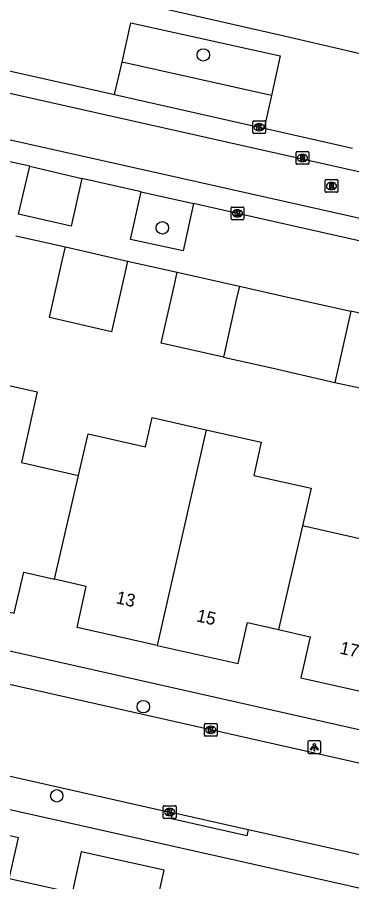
# Model space of a CAD drawing. Extents: x 161771 to 163125, y 382479 to 383177.
# Drawn here: x 162664.1 to 162690.4, y 382742 to 382809.9 of the extents above; entities that cross this region are included whole.
import ezdxf

# ---------------------------------------------------------------- set-up
doc = ezdxf.new("R2010")
doc.units = 0
for name, color, linetype in [('IMGEO_Boom', 7, 'Continuous'), ('IMGEO_Kolk', 7, 'Continuous'), ('IMGEO_Lichtpunt', 7, 'Continuous'), ('IMGEO_Pand', 7, 'Continuous'), ('IMGEO_Pand_nummerreeks', 7, 'Continuous'), ('IMGEO_Parkeervlak_open', 7, 'Continuous'), ('IMGEO_Rijbaan_lokaal_gesloten', 7, 'Continuous'), ('IMGEO_Rijbaan_lokaal_open', 7, 'Continuous'), ('IMGEO_Rioolput', 7, 'Continuous'), ('IMGEO_Voetpad_open', 7, 'Continuous')]:
    doc.layers.add(name, color=color, linetype=linetype)

msp = doc.modelspace()

# ---------------------------------------------------------------- linework, layer by layer
at = {"layer": 'IMGEO_Boom'}
for centre in [(162678.704, 382806.959), (162675.491, 382793.374), (162673.998, 382755.754), (162667.2, 382748.751)]:
    msp.add_circle(centre, 0.489, dxfattribs=at)
at = {"layer": 'IMGEO_Kolk'}
for p, q in [((162682.586, 382800.854), (162682.586, 382801.706)), ((162682.661, 382801.78), (162683.513, 382801.78)), ((162683.074, 382801.56), (162683.099, 382801.56)), ((162683.587, 382801.706), (162683.587, 382800.854)), ((162683.513, 382800.78), (162682.661, 382800.78)), ((162683.097, 382801), (162683.072, 382801)), ((162680.892, 382794.082), (162680.892, 382794.934)), ((162680.967, 382795.008), (162681.819, 382795.008)), ((162681.38, 382794.788), (162681.405, 382794.788)), ((162681.893, 382794.934), (162681.893, 382794.082)), ((162681.819, 382794.008), (162680.967, 382794.008)), ((162681.403, 382794.228), (162681.378, 382794.228)), ((162678.786, 382753.508), (162678.786, 382754.36)), ((162678.861, 382754.434), (162679.713, 382754.434)), ((162679.274, 382754.214), (162679.299, 382754.214)), ((162679.787, 382754.36), (162679.787, 382753.508)), ((162679.713, 382753.434), (162678.861, 382753.434)), ((162679.297, 382753.654), (162679.272, 382753.654)), ((162675.562, 382747.051), (162675.562, 382747.903)), ((162675.637, 382747.977), (162676.489, 382747.977)), ((162676.05, 382747.757), (162676.075, 382747.757)), ((162676.563, 382747.903), (162676.563, 382747.051)), ((162676.073, 382747.197), (162676.048, 382747.197)), ((162676.489, 382746.977), (162675.637, 382746.977))]:
    msp.add_line(p, q, dxfattribs=at)
for points in [[(162682.586, 382800.854), (162682.586, 382801.706)], [(162682.661, 382801.78), (162683.513, 382801.78)], [(162682.907, 382801.48), (162683.03, 382801.48), (162683.03, 382801.329), (162683.16, 382801.48), (162683.324, 382801.48), (162683.178, 382801.329), (162683.331, 382801.08), (162683.179, 382801.08), (162683.094, 382801.244), (162683.03, 382801.177), (162683.03, 382801.08), (162682.907, 382801.08), (162682.907, 382801.48)], [(162683.587, 382801.706), (162683.587, 382800.854)], [(162683.513, 382800.78), (162682.661, 382800.78)], [(162680.892, 382794.082), (162680.892, 382794.934)], [(162680.967, 382795.008), (162681.819, 382795.008)], [(162681.213, 382794.708), (162681.336, 382794.708), (162681.336, 382794.557), (162681.466, 382794.708), (162681.63, 382794.708), (162681.484, 382794.557), (162681.637, 382794.308), (162681.485, 382794.308), (162681.4, 382794.472), (162681.336, 382794.405), (162681.336, 382794.308), (162681.213, 382794.308), (162681.213, 382794.708)], [(162681.893, 382794.934), (162681.893, 382794.082)], [(162681.819, 382794.008), (162680.967, 382794.008)], [(162678.786, 382753.508), (162678.786, 382754.36)], [(162678.861, 382754.434), (162679.713, 382754.434)], [(162679.107, 382754.134), (162679.23, 382754.134), (162679.23, 382753.983), (162679.36, 382754.134), (162679.524, 382754.134), (162679.378, 382753.983), (162679.531, 382753.734), (162679.379, 382753.734), (162679.294, 382753.898), (162679.23, 382753.831), (162679.23, 382753.734), (162679.107, 382753.734), (162679.107, 382754.134)], [(162679.787, 382754.36), (162679.787, 382753.508)], [(162679.713, 382753.434), (162678.861, 382753.434)], [(162675.562, 382747.051), (162675.562, 382747.903)], [(162675.637, 382747.977), (162676.489, 382747.977)], [(162676.563, 382747.903), (162676.563, 382747.051)], [(162675.883, 382747.677), (162676.006, 382747.677), (162676.006, 382747.526), (162676.136, 382747.677), (162676.3, 382747.677), (162676.154, 382747.526), (162676.307, 382747.277), (162676.155, 382747.277), (162676.07, 382747.441), (162676.006, 382747.374), (162676.006, 382747.277), (162675.883, 382747.277), (162675.883, 382747.677)], [(162676.489, 382746.977), (162675.637, 382746.977)]]:
    msp.add_lwpolyline(points, dxfattribs=at)
for centre, start, end in [((162682.663, 382801.704), 91.55205, 178.44795), ((162682.663, 382801.704), 91.55205, 178.44795), ((162683.511, 382801.704), 1.55205, 88.44795), ((162683.511, 382801.704), 1.55205, 88.44795), ((162682.663, 382800.856), 181.55205, 268.44795), ((162682.663, 382800.856), 181.55205, 268.44795), ((162683.511, 382800.856), 271.55205, 358.44795), ((162683.511, 382800.856), 271.55205, 358.44795), ((162680.969, 382794.932), 91.55205, 178.44795), ((162680.969, 382794.932), 91.55205, 178.44795), ((162681.817, 382794.932), 1.55205, 88.44795), ((162681.817, 382794.932), 1.55205, 88.44795), ((162680.969, 382794.084), 181.55205, 268.44795), ((162680.969, 382794.084), 181.55205, 268.44795), ((162681.817, 382794.084), 271.55205, 358.44795), ((162681.817, 382794.084), 271.55205, 358.44795), ((162678.863, 382754.358), 91.55205, 178.44795), ((162678.863, 382754.358), 91.55205, 178.44795), ((162679.711, 382754.358), 1.55205, 88.44795), ((162679.711, 382754.358), 1.55205, 88.44795), ((162678.863, 382753.51), 181.55205, 268.44795), ((162678.863, 382753.51), 181.55205, 268.44795), ((162679.711, 382753.51), 271.55205, 358.44795), ((162679.711, 382753.51), 271.55205, 358.44795), ((162675.639, 382747.901), 91.55205, 178.44795), ((162675.639, 382747.901), 91.55205, 178.44795), ((162676.487, 382747.901), 1.55205, 88.44795), ((162676.487, 382747.901), 1.55205, 88.44795), ((162675.639, 382747.053), 181.55205, 268.44795), ((162675.639, 382747.053), 181.55205, 268.44795), ((162676.487, 382747.053), 271.55205, 358.44795), ((162676.487, 382747.053), 271.55205, 358.44795)]:
    msp.add_arc(centre, 0.0765, start, end, dxfattribs=at)
for centre, major_axis, ratio, start_param, end_param in [((162683.073, 382801.28), (-0.387, 0.002), 0.722429, 4.712389, 7.853982), ((162683.098, 382801.28), (-0.39, 0.002), 0.717154, 1.570796, 4.712389), ((162681.379, 382794.508), (-0.387, 0.002), 0.722429, 4.712389, 7.853982), ((162681.404, 382794.508), (-0.39, 0.002), 0.717154, 1.570796, 4.712389), ((162679.273, 382753.934), (-0.387, 0.002), 0.722429, 4.712389, 7.853982), ((162679.298, 382753.934), (-0.39, 0.002), 0.717154, 1.570796, 4.712389), ((162676.049, 382747.477), (-0.387, 0.002), 0.722429, 4.712389, 7.853982), ((162676.074, 382747.477), (-0.39, 0.002), 0.717154, 1.570796, 4.712389)]:
    msp.add_ellipse(centre, major_axis=major_axis, ratio=ratio, start_param=start_param, end_param=end_param, dxfattribs=at)
at = {"layer": 'IMGEO_Lichtpunt'}
for p, q in [((162686.923, 382752.978), (162686.923, 382752.171)), ((162686.923, 382752.978), (162686.923, 382752.171)), ((162687.825, 382753.073), (162687.017, 382753.073)), ((162687.825, 382753.073), (162687.017, 382753.073)), ((162687.919, 382752.171), (162687.919, 382752.978)), ((162687.919, 382752.171), (162687.919, 382752.978)), ((162687.017, 382752.077), (162687.825, 382752.077)), ((162687.017, 382752.077), (162687.825, 382752.077))]:
    msp.add_line(p, q, dxfattribs=at)
for points in [[(162687.297, 382752.642), (162687.336, 382752.614), (162687.148, 382752.352), (162687.11, 382752.379), (162687.297, 382752.642)], [(162687.399, 382752.594), (162687.446, 382752.594), (162687.446, 382752.272), (162687.399, 382752.272), (162687.399, 382752.594)], [(162687.509, 382752.614), (162687.547, 382752.641), (162687.734, 382752.379), (162687.695, 382752.351), (162687.509, 382752.614)]]:
    msp.add_lwpolyline(points, dxfattribs=at)
msp.add_circle((162687.422, 382752.776), 0.0994, dxfattribs=at)
for centre, start, end in [((162687.017, 382752.978), 90, 180), ((162687.017, 382752.978), 90, 180), ((162687.825, 382752.978), 0, 90), ((162687.825, 382752.978), 0, 90), ((162687.017, 382752.171), 180, 270), ((162687.017, 382752.171), 180, 270), ((162687.825, 382752.171), 270, 0), ((162687.825, 382752.171), 270, 360)]:
    msp.add_arc(centre, 0.0946, start, end, dxfattribs=at)
at = {"layer": 'IMGEO_Pand'}
for points in [[(162672.76, 382790.762), (162672.514, 382789.669), (162671.509, 382785.202), (162666.628, 382786.325), (162667.633, 382790.793), (162667.879, 382791.885)], [(162667.879, 382791.885), (162672.76, 382790.762)], [(162680.282, 382783.204), (162675.406, 382784.326), (162676.411, 382788.793), (162676.657, 382789.886)], [(162676.657, 382789.886), (162681.541, 382788.799)], [(162681.541, 382788.799), (162681.295, 382787.707), (162680.282, 382783.204)], [(162681.541, 382788.799), (162685.433, 382787.914), (162690.298, 382786.827)], [(162690.298, 382786.827), (162689.039, 382781.236)], [(162699.098, 382784.822), (162694.217, 382785.945), (162690.298, 382786.827)], [(162680.282, 382783.204), (162684.182, 382782.354), (162689.039, 382781.236)], [(162661.453, 382781.444), (162665.669, 382780.495), (162664.419, 382774.934), (162668.911, 382773.924)], [(162689.039, 382781.236), (162692.966, 382780.385), (162693.545, 382780.252), (162692.254, 382774.515), (162691.004, 382768.954), (162686.501, 382769.967)], [(162668.911, 382773.924), (162669.659, 382777.18), (162674.166, 382776.167), (162674.683, 382778.468), (162678.94, 382777.51)], [(162678.94, 382777.51), (162675.082, 382760.567)], [(162678.94, 382777.51), (162683.249, 382776.541), (162682.662, 382773.928), (162687.165, 382772.915), (162686.501, 382769.967)], [(162667.031, 382765.765), (162668.911, 382773.924)], [(162686.501, 382769.967), (162684.61, 382761.808)], [(162657.549, 382764.513), (162663.861, 382763.093), (162664.603, 382766.312), (162667.031, 382765.765)], [(162675.082, 382760.567), (162668.794, 382761.982), (162669.52, 382765.205), (162667.031, 382765.765)], [(162675.082, 382760.567), (162681.44, 382759.137), (162682.173, 382762.357), (162684.61, 382761.808)], [(162684.61, 382761.808), (162687.1, 382761.248), (162686.374, 382758.026), (162692.669, 382756.609)], [(162665.955, 382741.686), (162663.475, 382742.24), (162664.194, 382745.46), (162657.734, 382746.937), (162656.532, 382741.659), (162653.794, 382742.271)], [(162677.22, 382737.05), (162674.452, 382737.668), (162675.622, 382742.908), (162669.123, 382744.359), (162668.404, 382741.139), (162665.955, 382741.686)]]:
    msp.add_lwpolyline(points, dxfattribs=at)
at = {"layer": 'IMGEO_Parkeervlak_open'}
msp.add_lwpolyline([(162684.05, 382803.775), (162672.334, 382806.402)], dxfattribs=at)
at = {"layer": 'IMGEO_Rijbaan_lokaal_gesloten'}
for points in [[(163032.655, 382721.102), (163031.99, 382721.234), (162915.446, 382747.394), (162896.465, 382751.616), (162702.573, 382795.147), (162642.274, 382808.681), (162613.961, 382815.02), (162554.685, 382828.334), (162522.166, 382835.638)], [(162521.175, 382832.265), (162544.4, 382827.043), (162605.633, 382813.283), (162678.397, 382796.971), (162861.402, 382755.875), (162976.631, 382730.027), (163031.336, 382717.589), (163033.334, 382716.946), (163046.945, 382712.072)], [(162657.119, 382807.13), (162663.122, 382805.786), (162671.745, 382803.849)], [(162671.745, 382803.849), (162683.087, 382801.28), (162683.496, 382801.201)], [(162683.496, 382801.201), (162690.413, 382799.645)], [(162665.083, 382798.215), (162661.437, 382798.995), (162660.396, 382799.225)], [(162665.083, 382798.215), (162669.171, 382797.254)], [(162673.815, 382796.214), (162669.171, 382797.254)], [(162673.815, 382796.214), (162677.944, 382795.284)], [(162700.129, 382790.295), (162681.393, 382794.508), (162677.944, 382795.284)]]:
    msp.add_lwpolyline(points, dxfattribs=at)
at = {"layer": 'IMGEO_Rijbaan_lokaal_open'}
for points in [[(162713.275, 382746.266), (162699.386, 382749.405), (162697.208, 382749.88), (162691.396, 382751.216), (162679.283, 382753.935), (162659.284, 382758.448), (162641.175, 382762.541), (162623.101, 382766.566), (162611.096, 382769.288)], [(162658.611, 382751.42), (162658.807, 382751.353), (162664.834, 382750), (162676.068, 382747.478), (162676.306, 382747.443)], [(162676.306, 382747.443), (162682.23, 382746.098)], [(162682.23, 382746.098), (162683.061, 382745.932), (162695.747, 382743.076), (162697.911, 382742.57), (162700.86, 382741.914)]]:
    msp.add_lwpolyline(points, dxfattribs=at)
at = {"layer": 'IMGEO_Rioolput'}
for p, q in [((162686.062, 382799.366), (162686.914, 382799.366)), ((162685.987, 382798.44), (162685.987, 382799.292)), ((162686.475, 382799.146), (162686.5, 382799.146)), ((162686.988, 382799.292), (162686.988, 382798.44)), ((162686.914, 382798.366), (162686.062, 382798.366)), ((162686.498, 382798.586), (162686.473, 382798.586)), ((162688.265, 382796.238), (162688.265, 382797.09)), ((162688.34, 382797.164), (162689.192, 382797.164)), ((162688.753, 382796.944), (162688.778, 382796.944)), ((162689.266, 382797.09), (162689.266, 382796.238)), ((162689.192, 382796.164), (162688.34, 382796.164)), ((162688.776, 382796.384), (162688.751, 382796.384))]:
    msp.add_line(p, q, dxfattribs=at)
for points in [[(162686.062, 382799.366), (162686.914, 382799.366)], [(162685.987, 382798.44), (162685.987, 382799.292)], [(162686.576, 382799.064), (162686.324, 382799.066), (162686.324, 382798.666)], [(162686.324, 382798.666), (162686.448, 382798.666), (162686.448, 382798.828), (162686.459, 382798.828)], [(162686.502, 382798.985), (162686.448, 382798.985), (162686.448, 382798.904)], [(162686.448, 382798.904), (162686.5, 382798.904)], [(162686.506, 382798.799), (162686.577, 382798.666), (162686.717, 382798.666), (162686.652, 382798.792)], [(162686.988, 382799.292), (162686.988, 382798.44)], [(162686.914, 382798.366), (162686.062, 382798.366)], [(162688.265, 382796.238), (162688.265, 382797.09)], [(162688.34, 382797.164), (162689.192, 382797.164)], [(162688.854, 382796.862), (162688.602, 382796.864), (162688.602, 382796.464)], [(162688.78, 382796.783), (162688.726, 382796.783), (162688.726, 382796.702)], [(162688.726, 382796.702), (162688.778, 382796.702)], [(162689.266, 382797.09), (162689.266, 382796.238)], [(162689.192, 382796.164), (162688.34, 382796.164)], [(162688.602, 382796.464), (162688.726, 382796.464), (162688.726, 382796.626), (162688.737, 382796.626)], [(162688.784, 382796.597), (162688.855, 382796.464), (162688.995, 382796.464), (162688.93, 382796.59)]]:
    msp.add_lwpolyline(points, dxfattribs=at)
for centre, radius, start, end in [((162686.064, 382799.29), 0.0765, 91.55205, 178.44795), ((162686.064, 382799.29), 0.0765, 91.55205, 178.44795), ((162686.912, 382799.29), 0.0765, 1.55205, 88.44795), ((162686.912, 382799.29), 0.0765, 1.55205, 88.44795), ((162686.458, 382798.775), 0.0533, 26.02933, 88.69889), ((162686.484, 382799.093), 0.19, 274.7715, 282.96867), ((162686.508, 382798.889), 0.0964, 77.00612, 93.18647), ((162686.522, 382798.946), 0.0378, 276.66336, 79.67722), ((162686.575, 382798.954), 0.109, 350.36119, 89.41601), ((162686.573, 382798.954), 0.112, 277.58423, 350.98172), ((162686.557, 382798.739), 0.108, 29.51342, 73.79051), ((162686.064, 382798.442), 0.0765, 181.55205, 268.44795), ((162686.064, 382798.442), 0.0765, 181.55205, 268.44795), ((162686.912, 382798.442), 0.0765, 271.55205, 358.44795), ((162686.912, 382798.442), 0.0765, 271.55205, 358.44795), ((162688.342, 382797.088), 0.0765, 91.55205, 178.44795), ((162688.342, 382797.088), 0.0765, 91.55205, 178.44795), ((162688.762, 382796.891), 0.19, 274.7715, 282.96867), ((162688.786, 382796.687), 0.0964, 77.00612, 93.18647), ((162688.8, 382796.744), 0.0378, 276.66336, 79.67722), ((162688.853, 382796.752), 0.109, 350.36119, 89.41601), ((162688.851, 382796.752), 0.112, 277.58423, 350.98172), ((162688.835, 382796.537), 0.108, 29.51342, 73.79051), ((162689.19, 382797.088), 0.0765, 1.55205, 88.44795), ((162689.19, 382797.088), 0.0765, 1.55205, 88.44795), ((162688.342, 382796.24), 0.0765, 181.55205, 268.44795), ((162688.342, 382796.24), 0.0765, 181.55205, 268.44795), ((162688.736, 382796.573), 0.0533, 26.02933, 88.69889), ((162689.19, 382796.24), 0.0765, 271.55205, 358.44795), ((162689.19, 382796.24), 0.0765, 271.55205, 358.44795)]:
    msp.add_arc(centre, radius, start, end, dxfattribs=at)
for centre, major_axis, ratio, start_param, end_param in [((162686.474, 382798.866), (-0.387, 0.002), 0.722429, 4.712389, 7.853982), ((162686.499, 382798.866), (-0.39, 0.002), 0.717154, 1.570796, 4.712389), ((162688.752, 382796.664), (-0.387, 0.002), 0.722429, 4.712389, 7.853982), ((162688.777, 382796.664), (-0.39, 0.002), 0.717154, 1.570796, 4.712389)]:
    msp.add_ellipse(centre, major_axis=major_axis, ratio=ratio, start_param=start_param, end_param=end_param, dxfattribs=at)
at = {"layer": 'IMGEO_Voetpad_open'}
for points in [[(162816.205, 382779.202), (162801.958, 382782.393), (162792.029, 382784.598), (162756.754, 382792.433), (162738.248, 382796.544), (162732.951, 382797.721), (162727.832, 382798.858), (162721.08, 382800.358), (162691.456, 382806.938), (162684.715, 382808.504), (162683.095, 382808.88), (162666.477, 382812.67), (162660.607, 382814.009), (162659.934, 382813.924), (162647.054, 382816.755), (162640.833, 382818.172), (162609.155, 382825.277), (162605.495, 382826.112), (162601.822, 382826.906), (162592.09, 382829.137)], [(162672.334, 382806.402), (162673.022, 382809.491), (162684.752, 382806.878), (162684.05, 382803.775)], [(162671.745, 382803.849), (162672.334, 382806.402)], [(162684.05, 382803.775), (162683.496, 382801.201)], [(162669.171, 382797.254), (162668.323, 382793.518), (162664.206, 382794.436), (162665.083, 382798.215)], [(162677.944, 382795.284), (162677.124, 382791.565), (162672.976, 382792.452), (162673.815, 382796.214)], [(162663.996, 382792.746), (162667.879, 382791.885)], [(162672.76, 382790.762), (162676.657, 382789.886)], [(162727.249, 382745.732), (162722.81, 382746.736), (162697.675, 382752.409), (162692.083, 382753.675), (162614.078, 382771.241), (162612.565, 382771.591)], [(162623.348, 382756.657), (162631.971, 382754.731), (162653.103, 382750), (162681.631, 382743.624), (162695.338, 382740.54), (162700.264, 382739.423)], [(162682.23, 382746.098), (162682.12, 382745.611), (162676.196, 382746.956), (162676.306, 382747.443)]]:
    msp.add_lwpolyline(points, dxfattribs=at)

# ---------------------------------------------------------------- texts
at = {"layer": 'IMGEO_Pand_nummerreeks'}
for s, rotation, p in [('13', 347.32112, (162671.791, 382763.89)), ('15', 347.32112, (162678.114, 382762.468)), ('17', 347.31471, (162689.359, 382759.936))]:
    msp.add_text(s, height=1, rotation=rotation, dxfattribs=at).set_placement(p)

doc.saveas('drawing.dxf')
